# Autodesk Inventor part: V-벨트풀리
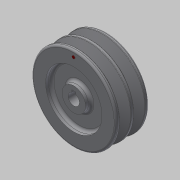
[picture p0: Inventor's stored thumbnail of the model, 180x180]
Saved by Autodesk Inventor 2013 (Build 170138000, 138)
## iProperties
Created: 2016-08
Part Number: V-벨트풀리
Material: 알루미늄 6061
Document SubType Name: Modeling
Designer: mduedu
Density: 2.71 g/cm^3
Author: mduedu
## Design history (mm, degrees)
sketch "스케치1"
  geometry: L1 (0, 17.5)-(0, -17.5); L2 (0, -17.5)-(45, -17.5); L3 (45, -17.5)-(45, 17.5); L4 (45, 17.5)-(0, 17.5); L5 (45, -1.524)-(32.5, -5.346); L6 (32.5, -5.346)-(32.5, -9.654); L7 (32.5, -9.654)-(45, -13.476); L8 (45, 13.476)-(32.5, 9.654); L9 (32.5, 9.654)-(32.5, 5.346); L10 (32.5, 5.346)-(45, 1.524); L11 (40.5, 17.5)-(40.5, -17.5); L12 (45, -7.5)-(0, -7.5); L13 (45, 7.5)-(0, 7.5); 8 further points
  constraints: 26 end point, 20 point on line, 6 perpendicular, 3 equal length, 3 midpoint, 2 collinear, 1 coincident, 1 horizontal, 1 vertical
  dimensions: "d43" = 90 diameter of L3 L1; "d45" = 34 deg angle of L7 L5; "d47" = 34 deg angle of L8 L10; "d49" = 9.2 distance of point (40.5, -12.1) point (40.5, -2.9); "d50" = 9.2 distance of point (40.5, 12.1) point (40.5, 2.9) (derived); "d51" = 10 distance between parallel lines of L12 L2; "d52" = 10 distance between parallel lines of L13 L4; "d53" = 15 distance between parallel lines of L12 L13; "d54" = 4.5 distance between parallel lines of L11 L3; "d55" = 8 distance between parallel lines of L6 L11
revolve "회전1" sketch "스케치1" stored, may be unused: angle "d8" = 90 deg
sketch "스케치2"
  geometry: L1 (-2, 0)-(2, 0); L2 (2, 0)-(2, 7.8); L3 (2, 7.8)-(-2, 7.8); L4 (-2, 7.8)-(-2, 0); C1 r 6 at (0, 0); 3 further points
  constraints: 8 end point, 3 coincident, 2 parallel, 1 centre point, 1 horizontal, 1 midpoint, 1 perpendicular
  dimensions: "d9" = 12 diameter of C1; "d11" = 4 distance of L2.end L3.end; "d12" = 7.8 distance of L1.end L2.end
extrude "돌출1" cut sketch "스케치2" stored distance "d13" = 10; taper "d14" = 0 deg
sketch "스케치4"
  geometry: C1 r 30 at (0, 0); C2 r 12.5 at (0, 0); 2 further points
  constraints: 3 coincident, 2 centre point
  dimensions: "d30" = 60 diameter of C1; "d31" = 25 diameter of C2
extrude "돌출2" cut sketch "스케치4" distance "d32" = 6; taper "d33" = 0 deg
fillet "모깎기6" dims "d34" = 3
fillet "모깎기8" dims "d56" = 0.5, "d57" = 1, "d58" = 2
chamfer "모따기1" distance "d26" = 0.5; stored, may be unused: second distance "d27" = 2, angle "d28" = 45 deg
sketch "스케치5" dims "d38" = 78
  geometry: C1 r 1.5 at (0, 39); 3 further points
  constraints: 2 coincident, 2 vertical alignment, 1 centre point, 2 other
  dimensions: "d40" = 3 diameter of C1
extrude "돌출3" join sketch "스케치5" distance "d41" = 0.5; taper "d42" = 0 deg
node "솔리드1"
mirror "대칭2"
